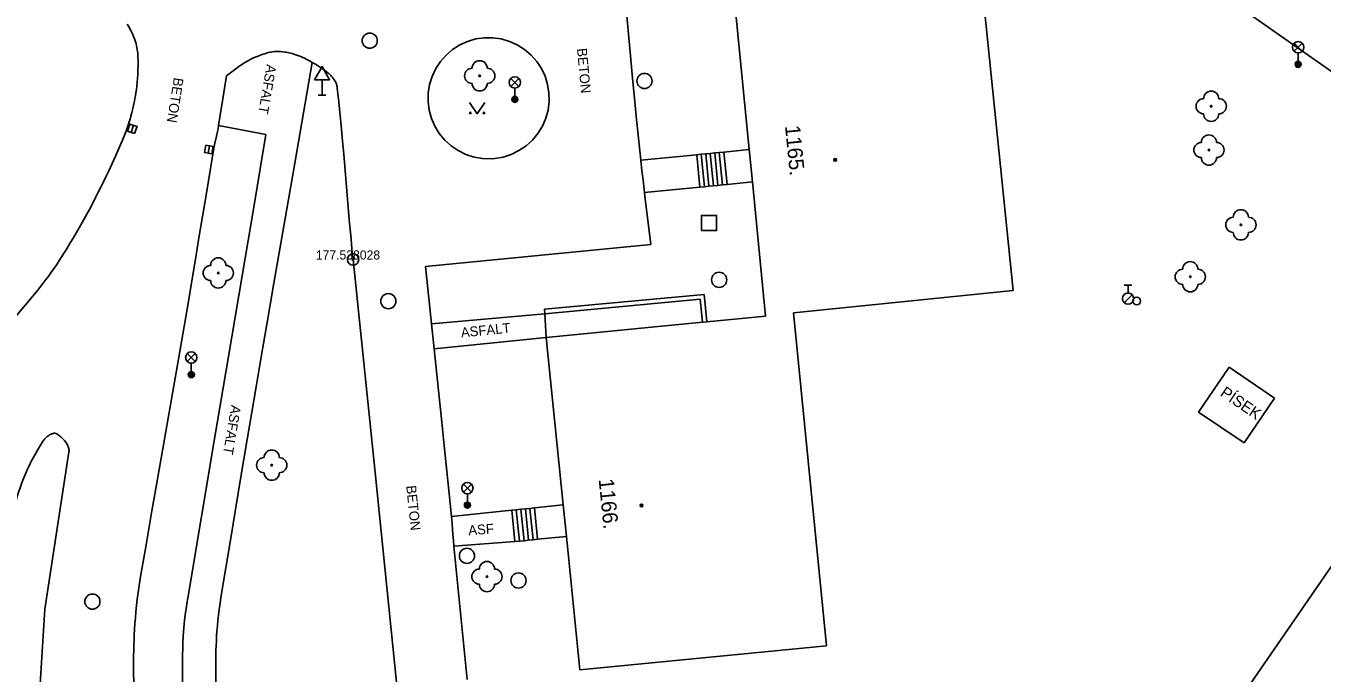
# Model space of a CAD drawing. Extents: x -539515 to -538098, y -1182060 to -1180157.
# Drawn here: x -538972.2 to -538886.7, y -1181281.4 to -1181238.7 of the extents above; entities that cross this region are included whole.
import ezdxf

# ---------------------------------------------------------------- set-up
doc = ezdxf.new("R2010")
doc.units = 0
for name, color, linetype in [('Vrstva 10', 7, 'Continuous'), ('Vrstva 11', 7, 'Continuous'), ('Vrstva 21', 7, 'Continuous'), ('Vrstva 22', 7, 'Continuous'), ('Vrstva 23', 7, 'Continuous'), ('Vrstva 26', 7, 'Continuous'), ('Vrstva 27', 7, 'Continuous'), ('Vrstva 28', 7, 'Continuous'), ('Vrstva 33', 7, 'Continuous'), ('Vrstva 34', 7, 'Continuous'), ('Vrstva 36', 7, 'Continuous'), ('Vrstva 39', 7, 'Continuous'), ('Vrstva 40', 7, 'Continuous'), ('Vrstva 41', 7, 'Continuous'), ('Vrstva 47', 7, 'Continuous'), ('Vrstva 5', 7, 'Continuous'), ('Vrstva 7', 7, 'Continuous')]:
    doc.layers.add(name, color=color, linetype=linetype)

msp = doc.modelspace()

# ---------------------------------------------------------------- linework, layer by layer
at = {"layer": 'Vrstva 10'}
for p, q in [((-538945.615, -1181244.214), (-538945.465, -1181244.759)), ((-538931.368, -1181249.898), (-538930.98, -1181253.09)), ((-538930.98, -1181253.09), (-538945.85, -1181254.54)), ((-538949.19, -1181268.145), (-538950.64, -1181254.08)), ((-538961.881, -1181259.016), (-538962.231, -1181261.033)), ((-538894.81, -1181264.15), (-538892.799, -1181261.187)), ((-538892.799, -1181261.187), (-538889.79, -1181263.23)), ((-538889.79, -1181263.23), (-538891.801, -1181266.193)), ((-538891.801, -1181266.193), (-538894.81, -1181264.15)), ((-538969.4, -1181266.8), (-538970.195, -1181271.98)), ((-538947.74, -1181282.21), (-538949.19, -1181268.145)), ((-538963.925, -1181270.682), (-538964.311, -1181272.916)), ((-538970.195, -1181271.98), (-538970.99, -1181277.16)), ((-538892.84, -1181284.195), (-538884.38, -1181271.91)), ((-538944.014, -1181272.633), (-538943.98, -1181273))]:
    msp.add_line(p, q, dxfattribs=at)
for points in [[(-538932.955, -1181233.705), (-538932.846, -1181234.923), (-538932.697, -1181236.541), (-538932.322, -1181240.62)], [(-538965.551, -1181238.535), (-538965.476, -1181238.661), (-538965.409, -1181238.779), (-538965.349, -1181238.889), (-538965.296, -1181238.993), (-538965.248, -1181239.091), (-538965.206, -1181239.183), (-538965.132, -1181239.355), (-538965.074, -1181239.507), (-538965.029, -1181239.64), (-538964.993, -1181239.757), (-538964.964, -1181239.86), (-538964.942, -1181239.95), (-538964.908, -1181240.109), (-538964.887, -1181240.228), (-538964.874, -1181240.318), (-538964.86, -1181240.454), (-538964.85, -1181240.59), (-538964.843, -1181240.764), (-538964.838, -1181240.932), (-538964.836, -1181241.096), (-538964.835, -1181241.256), (-538964.841, -1181241.566), (-538964.854, -1181241.857), (-538964.872, -1181242.131), (-538964.894, -1181242.389), (-538964.92, -1181242.631), (-538964.948, -1181242.857), (-538964.979, -1181243.07), (-538965.01, -1181243.27), (-538965.043, -1181243.456), (-538965.076, -1181243.632), (-538965.11, -1181243.796), (-538965.178, -1181244.102), (-538965.244, -1181244.37), (-538965.307, -1181244.604), (-538965.365, -1181244.807), (-538965.419, -1181244.985), (-538965.468, -1181245.14)], [(-538939.316, -1181240.209), (-538939.794, -1181239.906), (-538940.309, -1181239.674), (-538940.852, -1181239.516), (-538941.412, -1181239.437), (-538941.977, -1181239.437), (-538942.537, -1181239.517), (-538943.08, -1181239.676), (-538943.595, -1181239.909), (-538944.072, -1181240.212), (-538944.502, -1181240.58), (-538944.875, -1181241.004), (-538945.185, -1181241.477), (-538945.425, -1181241.989), (-538945.591, -1181242.529), (-538945.679, -1181243.088), (-538945.687, -1181243.653), (-538945.615, -1181244.214)], [(-538951.484, -1181244.596), (-538951.579, -1181243.678), (-538951.68, -1181242.76), (-538951.691, -1181242.687), (-538951.705, -1181242.619), (-538951.722, -1181242.554), (-538951.742, -1181242.493), (-538951.764, -1181242.435), (-538951.788, -1181242.379), (-538951.814, -1181242.327), (-538951.841, -1181242.277), (-538951.869, -1181242.23), (-538951.929, -1181242.141), (-538951.991, -1181242.06), (-538952.055, -1181241.987), (-538952.118, -1181241.92), (-538952.18, -1181241.859), (-538952.241, -1181241.803), (-538952.3, -1181241.752), (-538952.416, -1181241.658), (-538952.523, -1181241.579), (-538952.619, -1181241.511), (-538952.792, -1181241.396), (-538952.925, -1181241.312), (-538953.128, -1181241.19), (-538953.33, -1181241.07), (-538953.514, -1181240.965), (-538953.688, -1181240.872), (-538953.854, -1181240.79), (-538954.01, -1181240.719), (-538954.158, -1181240.656), (-538954.297, -1181240.602), (-538954.428, -1181240.555), (-538954.551, -1181240.515), (-538954.667, -1181240.481), (-538954.775, -1181240.452), (-538954.876, -1181240.428), (-538954.971, -1181240.408), (-538955.06, -1181240.391), (-538955.143, -1181240.378), (-538955.299, -1181240.358), (-538955.434, -1181240.347), (-538955.552, -1181240.342), (-538955.654, -1181240.342), (-538955.743, -1181240.345), (-538955.821, -1181240.35), (-538955.956, -1181240.364), (-538956.056, -1181240.379), (-538956.13, -1181240.393), (-538956.241, -1181240.419), (-538956.35, -1181240.45), (-538956.475, -1181240.49), (-538956.593, -1181240.53), (-538956.704, -1181240.569), (-538956.912, -1181240.649), (-538957.094, -1181240.724), (-538957.252, -1181240.795), (-538957.39, -1181240.86), (-538957.509, -1181240.92), (-538957.612, -1181240.975), (-538957.79, -1181241.075), (-538957.92, -1181241.155), (-538958.016, -1181241.216), (-538958.157, -1181241.313), (-538958.293, -1181241.414)], [(-538941.288, -1181247.409), (-538940.73, -1181247.312), (-538940.193, -1181247.137), (-538939.685, -1181246.889), (-538939.217, -1181246.572), (-538938.799, -1181246.191), (-538938.438, -1181245.756), (-538938.142, -1181245.274), (-538937.918, -1181244.755), (-538937.768, -1181244.21), (-538937.697, -1181243.649), (-538937.706, -1181243.083), (-538937.795, -1181242.525), (-538937.961, -1181241.984), (-538938.202, -1181241.473), (-538938.512, -1181241), (-538938.886, -1181240.576), (-538939.316, -1181240.209)], [(-538932.322, -1181240.62), (-538932.16, -1181242.349), (-538932.035, -1181243.644), (-538931.94, -1181244.616), (-538931.793, -1181246.073), (-538931.64, -1181247.53), (-538931.564, -1181248.226), (-538931.494, -1181248.834), (-538931.393, -1181249.665), (-538931.368, -1181249.898)], [(-538958.293, -1181241.414), (-538958.646, -1181241.687), (-538959, -1181241.96)], [(-538959, -1181241.96), (-538959.26, -1181243.6), (-538959.52, -1181245.24), (-538959.555, -1181245.444), (-538959.59, -1181245.621), (-538959.656, -1181245.931), (-538959.759, -1181246.394), (-538959.807, -1181246.627), (-538959.85, -1181246.86), (-538960.033, -1181247.937), (-538960.347, -1181249.822)], [(-538950.64, -1181254.08), (-538950.711, -1181253.373), (-538950.774, -1181252.71), (-538950.887, -1181251.467), (-538951.253, -1181247.113), (-538951.349, -1181246.024), (-538951.425, -1181245.208), (-538951.484, -1181244.596)], [(-538945.465, -1181244.759), (-538945.24, -1181245.278), (-538944.944, -1181245.759), (-538944.583, -1181246.194), (-538944.164, -1181246.574), (-538943.696, -1181246.891), (-538943.188, -1181247.139), (-538942.65, -1181247.313), (-538942.093, -1181247.409), (-538941.527, -1181247.426), (-538941.288, -1181247.409)], [(-538965.468, -1181245.14), (-538965.56, -1181245.41), (-538965.632, -1181245.612), (-538965.689, -1181245.762), (-538965.777, -1181245.987), (-538965.87, -1181246.21), (-538966.107, -1181246.757), (-538966.332, -1181247.265), (-538966.546, -1181247.736), (-538966.749, -1181248.174), (-538966.941, -1181248.581), (-538967.124, -1181248.96), (-538967.298, -1181249.313), (-538967.462, -1181249.642), (-538967.618, -1181249.949), (-538967.766, -1181250.235), (-538968.048, -1181250.769), (-538968.3, -1181251.232), (-538968.524, -1181251.635), (-538968.723, -1181251.986), (-538968.9, -1181252.292), (-538969.057, -1181252.559), (-538969.336, -1181253.024), (-538969.549, -1181253.372), (-538969.711, -1181253.632), (-538969.958, -1181254.022)], [(-538960.347, -1181249.822), (-538960.813, -1181252.651), (-538961.045, -1181254.066), (-538961.28, -1181255.48), (-538961.487, -1181256.71), (-538961.881, -1181259.016)], [(-538969.958, -1181254.022), (-538970.21, -1181254.41), (-538970.355, -1181254.628), (-538970.499, -1181254.836), (-538970.64, -1181255.035), (-538970.78, -1181255.227), (-538970.917, -1181255.41), (-538971.052, -1181255.587), (-538971.317, -1181255.925), (-538971.57, -1181256.238), (-538971.81, -1181256.53)], [(-538945.85, -1181254.54), (-538945.66, -1181256.435), (-538945.47, -1181258.33), (-538945.427, -1181258.74), (-538945.358, -1181259.355), (-538945.29, -1181259.97), (-538944.996, -1181262.737)], [(-538971.81, -1181256.53), (-538972.266, -1181257.071), (-538973.07, -1181258.013), (-538973.369, -1181258.368), (-538973.628, -1181258.681), (-538973.852, -1181258.957), (-538974.045, -1181259.201), (-538974.212, -1181259.416), (-538974.357, -1181259.606), (-538974.481, -1181259.773), (-538974.695, -1181260.07), (-538974.852, -1181260.295), (-538974.967, -1181260.466), (-538975.136, -1181260.726), (-538975.3, -1181260.99), (-538975.625, -1181261.532), (-538975.925, -1181262.042), (-538976.201, -1181262.524), (-538976.454, -1181262.977), (-538976.687, -1181263.405), (-538976.901, -1181263.808), (-538977.097, -1181264.188), (-538977.277, -1181264.545)], [(-538962.231, -1181261.033), (-538962.85, -1181264.562), (-538963.316, -1181267.209), (-538963.665, -1181269.193), (-538963.925, -1181270.682)], [(-538944.996, -1181262.737), (-538944.778, -1181264.812), (-538944.618, -1181266.368), (-538944.381, -1181268.704), (-538944.15, -1181271.04), (-538944.106, -1181271.53), (-538944.046, -1181272.265), (-538944.014, -1181272.633)], [(-538971.759, -1181267.181), (-538971.614, -1181266.916), (-538971.502, -1181266.717), (-538971.414, -1181266.568), (-538971.28, -1181266.344), (-538971.14, -1181266.12), (-538971.099, -1181266.059), (-538971.055, -1181266.002), (-538971.01, -1181265.948), (-538970.964, -1181265.899), (-538970.919, -1181265.854), (-538970.875, -1181265.813), (-538970.833, -1181265.777), (-538970.75, -1181265.713), (-538970.676, -1181265.665), (-538970.611, -1181265.628), (-538970.553, -1181265.601), (-538970.504, -1181265.582), (-538970.461, -1181265.569), (-538970.423, -1181265.561), (-538970.392, -1181265.557), (-538970.364, -1181265.555), (-538970.317, -1181265.556), (-538970.284, -1181265.561), (-538970.259, -1181265.568), (-538970.19, -1181265.6), (-538970.121, -1181265.647), (-538970.055, -1181265.696), (-538969.991, -1181265.746), (-538969.931, -1181265.797), (-538969.876, -1181265.847), (-538969.824, -1181265.896), (-538969.776, -1181265.945), (-538969.691, -1181266.039), (-538969.621, -1181266.127), (-538969.566, -1181266.206), (-538969.522, -1181266.277), (-538969.488, -1181266.34), (-538969.462, -1181266.396), (-538969.442, -1181266.446), (-538969.428, -1181266.49), (-538969.408, -1181266.567), (-538969.398, -1181266.625), (-538969.394, -1181266.669), (-538969.394, -1181266.734), (-538969.4, -1181266.8)], [(-538974.109, -1181274.707), (-538973.89, -1181273.76), (-538973.774, -1181273.276), (-538973.669, -1181272.853), (-538973.575, -1181272.485), (-538973.406, -1181271.843), (-538973.276, -1181271.362), (-538973.075, -1181270.641), (-538972.87, -1181269.92), (-538972.796, -1181269.67), (-538972.722, -1181269.438), (-538972.65, -1181269.222), (-538972.58, -1181269.022), (-538972.511, -1181268.835), (-538972.444, -1181268.661), (-538972.379, -1181268.499), (-538972.251, -1181268.197), (-538972.134, -1181267.935), (-538972.026, -1181267.706), (-538971.928, -1181267.507), (-538971.839, -1181267.333), (-538971.759, -1181267.181)], [(-538964.311, -1181272.916), (-538964.69, -1181275.15), (-538964.764, -1181275.614), (-538964.829, -1181276.065), (-538964.885, -1181276.502), (-538964.934, -1181276.926), (-538964.975, -1181277.338), (-538965.011, -1181277.737), (-538965.041, -1181278.124), (-538965.066, -1181278.5), (-538965.086, -1181278.864), (-538965.102, -1181279.217), (-538965.115, -1181279.559), (-538965.125, -1181279.891), (-538965.131, -1181280.213), (-538965.135, -1181280.525), (-538965.137, -1181280.827), (-538965.134, -1181281.413), (-538965.125, -1181281.962), (-538965.111, -1181282.478)], [(-538943.98, -1181273), (-538943.54, -1181277.405), (-538943.1, -1181281.81)], [(-538970.99, -1181277.16), (-538971.21, -1181280.69), (-538971.429, -1181284.22), (-538971.448, -1181284.561), (-538971.462, -1181284.882), (-538971.471, -1181285.182), (-538971.477, -1181285.463), (-538971.48, -1181285.728), (-538971.48, -1181286.223), (-538971.474, -1181286.656), (-538971.464, -1181287.036)]]:
    msp.add_lwpolyline(points, dxfattribs=at)
at = {"layer": 'Vrstva 11'}
for p, q in [((-538902.52, -1181230.08), (-538864.69, -1181256.7)), ((-538953.33, -1181241.07), (-538954.6, -1181248.355)), ((-538959.52, -1181245.24), (-538956.39, -1181245.83)), ((-538927.95, -1181247.161), (-538931.64, -1181247.53)), ((-538927.95, -1181247.161), (-538927.74, -1181249.3)), ((-538927.651, -1181247.131), (-538927.441, -1181249.27)), ((-538927.352, -1181247.102), (-538927.142, -1181249.241)), ((-538927.054, -1181247.073), (-538926.844, -1181249.212)), ((-538926.755, -1181247.043), (-538926.545, -1181249.182)), ((-538926.457, -1181247.014), (-538926.247, -1181249.153)), ((-538926.158, -1181246.985), (-538925.948, -1181249.124)), ((-538954.6, -1181248.355), (-538955.87, -1181255.64)), ((-538927.74, -1181249.3), (-538931.393, -1181249.665)), ((-538958.871, -1181260.474), (-538957.97, -1181255.15)), ((-538945.47, -1181258.33), (-538937.982, -1181257.669)), ((-538937.982, -1181257.669), (-538937.89, -1181259.24)), ((-538937.89, -1181259.24), (-538945.29, -1181259.97)), ((-538959.77, -1181265.799), (-538958.871, -1181260.474)), ((-538961.56, -1181276.45), (-538959.77, -1181265.799)), ((-538958.07, -1181268.568), (-538958.718, -1181272.479)), ((-538940.161, -1181270.634), (-538944.15, -1181271.04)), ((-538940.161, -1181270.634), (-538939.95, -1181272.71)), ((-538939.862, -1181270.603), (-538939.651, -1181272.679)), ((-538939.564, -1181270.573), (-538939.353, -1181272.649)), ((-538939.265, -1181270.542), (-538939.054, -1181272.618)), ((-538938.967, -1181270.512), (-538938.756, -1181272.588)), ((-538938.668, -1181270.482), (-538938.457, -1181272.558)), ((-538939.95, -1181272.71), (-538943.98, -1181273))]:
    msp.add_line(p, q, dxfattribs=at)
for points in [[(-538957.97, -1181255.15), (-538957.18, -1181250.49), (-538956.39, -1181245.83)], [(-538924.481, -1181246.82), (-538926.158, -1181246.985), (-538926.457, -1181247.014), (-538926.755, -1181247.043), (-538927.054, -1181247.073), (-538927.352, -1181247.102), (-538927.651, -1181247.131), (-538927.95, -1181247.161)], [(-538924.271, -1181248.959), (-538925.948, -1181249.124), (-538926.247, -1181249.153), (-538926.545, -1181249.182), (-538926.844, -1181249.212), (-538927.142, -1181249.241), (-538927.441, -1181249.27), (-538927.74, -1181249.3)], [(-538955.87, -1181255.64), (-538956.319, -1181258.232), (-538956.709, -1181260.5), (-538957.047, -1181262.485)], [(-538957.047, -1181262.485), (-538957.634, -1181265.961), (-538958.07, -1181268.568)], [(-538936.766, -1181270.289), (-538938.668, -1181270.482), (-538938.967, -1181270.512), (-538939.265, -1181270.542), (-538939.564, -1181270.573), (-538939.862, -1181270.603), (-538940.161, -1181270.634)], [(-538958.718, -1181272.479), (-538959.36, -1181276.39), (-538959.422, -1181276.791), (-538959.476, -1181277.181), (-538959.522, -1181277.559), (-538959.562, -1181277.925), (-538959.596, -1181278.281), (-538959.624, -1181278.626), (-538959.647, -1181278.96), (-538959.666, -1181279.285), (-538959.682, -1181279.599), (-538959.693, -1181279.904), (-538959.702, -1181280.2), (-538959.707, -1181280.487), (-538959.71, -1181280.765), (-538959.711, -1181281.034), (-538959.708, -1181281.556), (-538959.698, -1181282.046)], [(-538936.555, -1181272.365), (-538938.457, -1181272.558), (-538938.756, -1181272.588), (-538939.054, -1181272.618), (-538939.353, -1181272.649), (-538939.651, -1181272.679), (-538939.95, -1181272.71)], [(-538961.879, -1181282.402), (-538961.892, -1181282.028), (-538961.901, -1181281.677), (-538961.906, -1181281.348), (-538961.908, -1181281.04), (-538961.908, -1181280.751), (-538961.905, -1181280.481), (-538961.901, -1181280.227), (-538961.887, -1181279.752), (-538961.869, -1181279.338), (-538961.848, -1181278.975), (-538961.825, -1181278.658), (-538961.803, -1181278.381), (-538961.781, -1181278.139), (-538961.737, -1181277.715), (-538961.699, -1181277.398), (-538961.668, -1181277.161), (-538961.617, -1181276.805), (-538961.56, -1181276.45)]]:
    msp.add_lwpolyline(points, dxfattribs=at)
at = {"layer": 'Vrstva 21'}
for radius in [0.375, 0.05]:
    msp.add_circle((-538950.64, -1181254.08), radius, dxfattribs=at)
at = {"layer": 'Vrstva 22'}
for centre in [(-538942.28, -1181241.95), (-538893.98, -1181243.96), (-538894.13, -1181246.85), (-538892.02, -1181251.79), (-538959.54, -1181254.97), (-538895.36, -1181255.22), (-538956.01, -1181267.66), (-538941.8, -1181275.02)]:
    msp.add_circle(centre, 0.05, dxfattribs=at)
for centre, start, end in [((-538942.78, -1181241.95), 90, 270), ((-538942.28, -1181241.45), 0, 180), ((-538941.78, -1181241.95), 270, 90), ((-538942.28, -1181242.45), 180, 0), ((-538893.98, -1181243.46), 0, 180), ((-538894.48, -1181243.96), 90, 270), ((-538893.48, -1181243.96), 270, 90), ((-538893.98, -1181244.46), 180, 0), ((-538894.13, -1181246.35), 0, 180), ((-538894.63, -1181246.85), 90, 270), ((-538893.63, -1181246.85), 270, 90), ((-538894.13, -1181247.35), 180, 0), ((-538892.02, -1181251.29), 0, 180), ((-538892.52, -1181251.79), 90, 270), ((-538891.52, -1181251.79), 270, 90), ((-538892.02, -1181252.29), 180, 0), ((-538960.04, -1181254.97), 90, 270), ((-538959.54, -1181254.47), 0, 180), ((-538959.04, -1181254.97), 270, 90), ((-538895.36, -1181254.72), 0, 180), ((-538895.86, -1181255.22), 90, 270), ((-538894.86, -1181255.22), 270, 90), ((-538959.54, -1181255.47), 180, 0), ((-538895.36, -1181255.72), 180, 0), ((-538956.51, -1181267.66), 90, 270), ((-538956.01, -1181267.16), 0, 180), ((-538955.51, -1181267.66), 270, 90), ((-538956.01, -1181268.16), 180, 0), ((-538941.8, -1181274.52), 0, 180), ((-538942.3, -1181275.02), 90, 270), ((-538941.3, -1181275.02), 270, 90), ((-538941.8, -1181275.52), 180, 0)]:
    msp.add_arc(centre, 0.5, start, end, dxfattribs=at)
at = {"layer": 'Vrstva 26'}
msp.add_lwpolyline([(-538927.64, -1181252.17), (-538926.64, -1181252.17), (-538926.64, -1181251.17), (-538927.64, -1181251.17)], close=True, dxfattribs=at)
at = {"layer": 'Vrstva 27'}
for p, q in [((-538965.301, -1181245.686), (-538965.139, -1181245.214)), ((-538960.114, -1181246.571), (-538960.2, -1181247.063))]:
    msp.add_line(p, q, dxfattribs=at)
for points in [[(-538965.065, -1181245.768), (-538964.902, -1181245.295), (-538965.375, -1181245.132), (-538965.538, -1181245.605)], [(-538960.36, -1181246.527), (-538960.447, -1181247.02), (-538959.954, -1181247.107), (-538959.867, -1181246.614)]]:
    msp.add_lwpolyline(points, close=True, dxfattribs=at)
for centre in [(-538949.54, -1181239.63), (-538931.4, -1181242.29), (-538926.47, -1181255.42), (-538948.31, -1181256.83), (-538943.12, -1181273.65), (-538939.72, -1181275.28), (-538967.85, -1181276.67)]:
    msp.add_circle(centre, 0.5, dxfattribs=at)
at = {"layer": 'Vrstva 28'}
for p, q in [((-538899.72, -1181255.785), (-538899.22, -1181255.785)), ((-538899.47, -1181256.285), (-538899.47, -1181255.785)), ((-538899.728, -1181256.932), (-538899.198, -1181256.402))]:
    msp.add_line(p, q, dxfattribs=at)
for centre, radius in [((-538899.47, -1181256.66), 0.375), ((-538898.9, -1181256.82), 0.25)]:
    msp.add_circle(centre, radius, dxfattribs=at)
at = {"layer": 'Vrstva 33'}
for p, q in [((-538888.505, -1181240.33), (-538887.975, -1181239.8)), ((-538888.505, -1181239.8), (-538887.975, -1181240.33)), ((-538888.24, -1181240.44), (-538888.24, -1181241.19)), ((-538940.225, -1181242.65), (-538939.695, -1181242.12)), ((-538940.225, -1181242.12), (-538939.695, -1181242.65)), ((-538939.96, -1181242.76), (-538939.96, -1181243.51)), ((-538961.585, -1181260.82), (-538961.055, -1181260.29)), ((-538961.585, -1181260.29), (-538961.055, -1181260.82)), ((-538961.32, -1181260.93), (-538961.32, -1181261.68)), ((-538943.355, -1181269.44), (-538942.825, -1181268.91)), ((-538943.355, -1181268.91), (-538942.825, -1181269.44)), ((-538943.09, -1181269.55), (-538943.09, -1181270.3))]:
    msp.add_line(p, q, dxfattribs=at)
for centre, radius in [((-538888.24, -1181240.065), 0.375), ((-538888.24, -1181241.19), 0.2), ((-538888.24, -1181241.19), 0.145), ((-538888.24, -1181241.19), 0.0876), ((-538939.96, -1181242.385), 0.375), ((-538939.96, -1181243.51), 0.2), ((-538939.96, -1181243.51), 0.145), ((-538939.96, -1181243.51), 0.0876), ((-538961.32, -1181260.555), 0.375), ((-538961.32, -1181261.68), 0.2), ((-538961.32, -1181261.68), 0.145), ((-538961.32, -1181261.68), 0.0876), ((-538943.09, -1181269.175), 0.375), ((-538943.09, -1181270.3), 0.2), ((-538943.09, -1181270.3), 0.145), ((-538943.09, -1181270.3), 0.0876)]:
    msp.add_circle(centre, radius, dxfattribs=at)
at = {"layer": 'Vrstva 34'}
for p, q in [((-538952.691, -1181242.208), (-538952.691, -1181243.226)), ((-538952.941, -1181243.226), (-538952.441, -1181243.226))]:
    msp.add_line(p, q, dxfattribs=at)
msp.add_lwpolyline([(-538953.191, -1181242.208), (-538952.191, -1181242.208), (-538952.691, -1181241.342)], close=True, dxfattribs=at)
at = {"layer": 'Vrstva 36'}
msp.add_lwpolyline([(-538942.943, -1181243.701), (-538942.443, -1181244.451), (-538941.943, -1181243.701)], dxfattribs=at)
for centre in [(-538942.893, -1181244.401), (-538941.994, -1181244.401)]:
    msp.add_circle(centre, 0.05, dxfattribs=at)
at = {"layer": 'Vrstva 39'}
for centre, radius in [((-538918.8, -1181247.504), 0.09), ((-538918.8, -1181247.504), 0.0398), ((-538931.589, -1181270.321), 0.09), ((-538931.589, -1181270.321), 0.0398)]:
    msp.add_circle(centre, radius, dxfattribs=at)
at = {"layer": 'Vrstva 5'}
for p, q in [((-538907.06, -1181256.12), (-538909.29, -1181234.2)), ((-538925.56, -1181235.84), (-538924.481, -1181246.82)), ((-538924.481, -1181246.82), (-538924.271, -1181248.959)), ((-538924.271, -1181248.959), (-538923.4, -1181257.82)), ((-538921.57, -1181257.6), (-538907.06, -1181256.12)), ((-538927.272, -1181258.199), (-538923.4, -1181257.82)), ((-538919.39, -1181279.59), (-538921.57, -1181257.6)), ((-538937.89, -1181259.24), (-538927.571, -1181258.228)), ((-538927.571, -1181258.228), (-538927.272, -1181258.199)), ((-538936.766, -1181270.289), (-538937.89, -1181259.24)), ((-538936.555, -1181272.365), (-538936.766, -1181270.289)), ((-538935.66, -1181281.17), (-538936.555, -1181272.365)), ((-538919.39, -1181279.59), (-538935.66, -1181281.17))]:
    msp.add_line(p, q, dxfattribs=at)
at = {"layer": 'Vrstva 7'}
for p, q in [((-538927.45, -1181256.38), (-538938.01, -1181257.37)), ((-538937.982, -1181257.669), (-538927.719, -1181256.707)), ((-538927.719, -1181256.707), (-538927.571, -1181258.228)), ((-538927.272, -1181258.199), (-538927.45, -1181256.38)), ((-538938.01, -1181257.37), (-538937.982, -1181257.669))]:
    msp.add_line(p, q, dxfattribs=at)

# ---------------------------------------------------------------- texts
at = {"layer": 'Vrstva 22'}
msp.add_text('177.53 ', height=0.6, dxfattribs=at).set_placement((-538953.097, -1181254.08))
at = {"layer": 'Vrstva 23'}
msp.add_text('8028', height=0.6, dxfattribs=at).set_placement((-538950.64, -1181254.08))
at = {"layer": 'Vrstva 40'}
for s, rotation, p in [('BETON', 275.30013, (-538935.857, -1181240.152)), ('ASFALT', 260.11096, (-538956.34, -1181241.165)), ('BETON', 260.9915, (-538962.467, -1181242.033)), ('ASFALT', 5.63392, (-538943.488, -1181259.229)), ('ASFALT', 260.43279, (-538958.678, -1181263.661)), ('BETON', 275.88599, (-538947.133, -1181269.028)), ('ASF', 4.11592, (-538943.009, -1181272.292))]:
    msp.add_text(s, height=0.65, rotation=rotation, dxfattribs=at).set_placement(p)
at = {"layer": 'Vrstva 41'}
msp.add_text('PÍSEK', height=0.75, rotation=325.82494, dxfattribs=at).set_placement((-538893.443, -1181263.034))
at = {"layer": 'Vrstva 47'}
for s, rotation, p in [('1165.', 275.6125, (-538922.122, -1181245.257)), ('1166.', 275.80629, (-538934.426, -1181268.597))]:
    msp.add_text(s, height=1, rotation=rotation, dxfattribs=at).set_placement(p)

doc.saveas('drawing.dxf')
